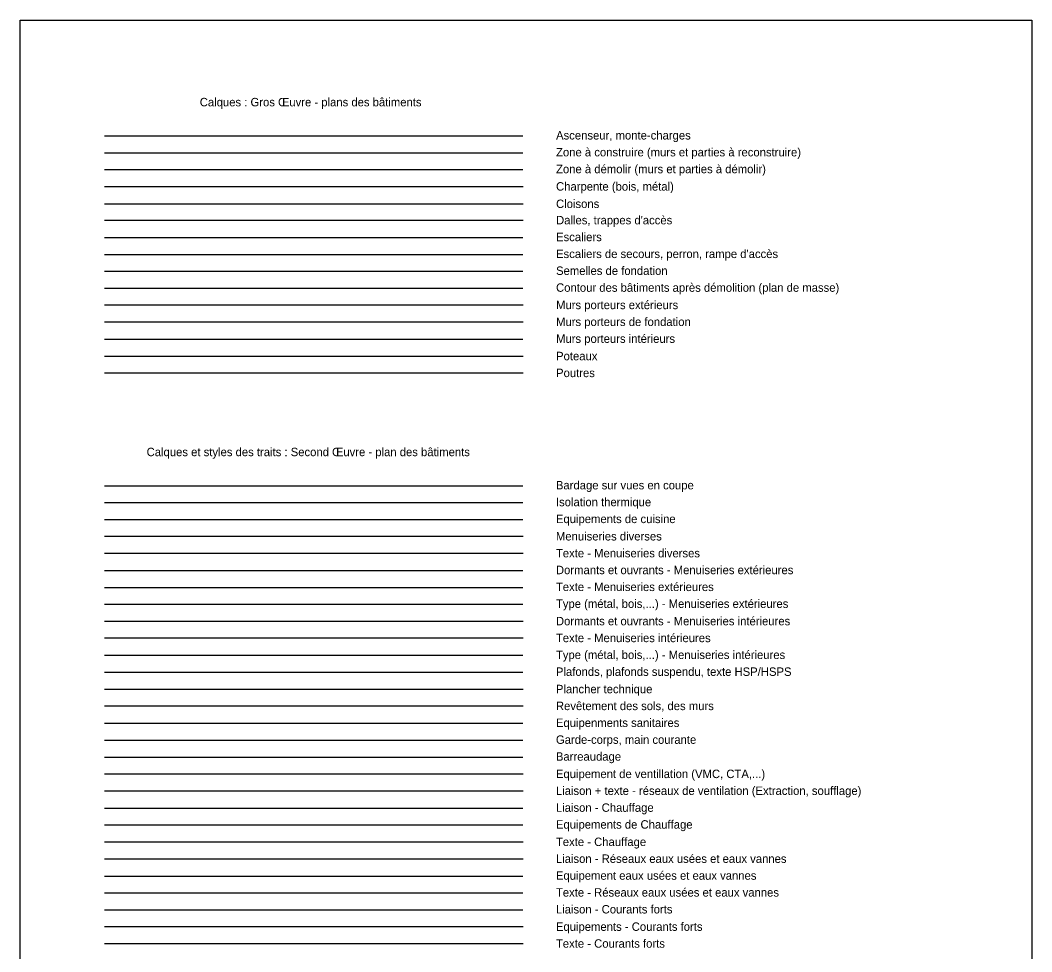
# Model space of a CAD drawing. Extents: x 703432 to 707394, y 7057985 to 7059523.
# Drawn here: x 707334.5 to 707394.5, y 7058589.3 to 7058644.6 of the extents above; entities that cross this region are included whole.
import ezdxf

# ---------------------------------------------------------------- set-up
doc = ezdxf.new("R2010")
doc.units = 0
for name, color, linetype in [('DH_CADRE -CARTOUCHE', 7, 'Continuous'), ('GO_A CONSTRUIRE', 7, 'Continuous'), ('GO_A DEMOLIR', 7, 'Continuous'), ('GO_ASCENSEUR', 7, 'Continuous'), ('GO_BATIMENT_DEMOLI', 7, 'Continuous'), ('GO_CHARPENTE', 7, 'Continuous'), ('GO_CLOISON', 7, 'Continuous'), ('GO_DALLE', 7, 'Continuous'), ('GO_ESCALIER_EXTERIEUR', 7, 'Continuous'), ('GO_ESCALIER_INTERIEUR', 7, 'Continuous'), ('GO_FONDATION', 7, 'Continuous'), ('GO_MUR_EXTERIEUR', 7, 'Continuous'), ('GO_MUR_FONDATION', 7, 'Continuous'), ('GO_MUR_INTERIEUR', 7, 'Continuous'), ('GO_POTEAU', 7, 'Continuous'), ('GO_POUTRE', 7, 'Continuous'), ('SO_BARDAGE', 7, 'Continuous'), ('SO_BARREAUDAGE', 7, 'Continuous'), ('SO_CHAUFFAGE_EQUIP', 7, 'Continuous'), ('SO_CHAUFFAGE_LIAISON', 7, 'Continuous'), ('SO_CHAUFFAGE_TEXTE', 7, 'Continuous'), ('SO_ELEC_C_FORTS_EQUIP', 7, 'Continuous'), ('SO_ELEC_C_FORTS_LIAISON', 7, 'Continuous'), ('SO_ELEC_C_FORTS_TEXTE', 7, 'Continuous'), ('SO_EQUIP_CUISINE', 7, 'Continuous'), ('SO_EU_EV_EQUIP', 7, 'Continuous'), ('SO_EU_EV_LIAISON', 7, 'Continuous'), ('SO_EU_EV_TEXTE', 7, 'Continuous'), ('SO_GARDE_CORPS', 7, 'Continuous'), ('SO_ISOLATION', 7, 'Continuous'), ('SO_MENUISERIE DIVERS_EQUIP', 7, 'Continuous'), ('SO_MENUISERIE DIVERS_TEXTE', 7, 'Continuous'), ('SO_MENUISERIE EXT_ EQUIP', 7, 'Continuous'), ('SO_MENUISERIE EXT_TEXTE', 7, 'Continuous'), ('SO_MENUISERIE EXT_TYPE', 7, 'Continuous'), ('SO_MENUISERIE INT_ EQUIP', 7, 'Continuous'), ('SO_MENUISERIE INT_TEXTE', 7, 'Continuous'), ('SO_MENUISERIE INT_TYPE', 7, 'Continuous'), ('SO_PLAFOND', 7, 'Continuous'), ('SO_PLANCHER TECHNIQUE', 7, 'Continuous'), ('SO_REVETEMENT_SOL_MUR', 7, 'Continuous'), ('SO_SANITAIRE', 7, 'Continuous'), ('SO_VMC_CVC_CTA_EQUIP', 7, 'Continuous'), ('SO_VMC_CVC_CTA_RES-TEXTE', 7, 'Continuous')]:
    doc.layers.add(name, color=color, linetype=linetype)

msp = doc.modelspace()

# ---------------------------------------------------------------- linework, layer by layer
at = {"layer": 'DH_CADRE -CARTOUCHE'}
msp.add_lwpolyline([(707334.469, 7058644.551), (707394.469, 7058644.551), (707394.469, 7058534.551), (707334.469, 7058534.551)], close=True, dxfattribs=at)
at = {"layer": 'GO_A CONSTRUIRE'}
msp.add_line((707339.469, 7058636.694), (707364.284, 7058636.694), dxfattribs=at)
at = {"layer": 'GO_A DEMOLIR'}
msp.add_line((707339.469, 7058635.694), (707364.284, 7058635.694), dxfattribs=at)
at = {"layer": 'GO_ASCENSEUR'}
msp.add_line((707339.469, 7058637.694), (707364.284, 7058637.694), dxfattribs=at)
at = {"layer": 'GO_BATIMENT_DEMOLI'}
msp.add_line((707339.469, 7058628.663), (707364.284, 7058628.663), dxfattribs=at)
at = {"layer": 'GO_CHARPENTE'}
msp.add_line((707339.469, 7058634.694), (707364.298, 7058634.694), dxfattribs=at)
at = {"layer": 'GO_CLOISON'}
msp.add_line((707339.469, 7058633.663), (707364.298, 7058633.663), dxfattribs=at)
at = {"layer": 'GO_DALLE'}
msp.add_line((707339.469, 7058632.694), (707364.298, 7058632.694), dxfattribs=at)
at = {"layer": 'GO_ESCALIER_EXTERIEUR'}
msp.add_line((707339.469, 7058630.663), (707364.284, 7058630.663), dxfattribs=at)
at = {"layer": 'GO_ESCALIER_INTERIEUR'}
msp.add_line((707339.469, 7058631.663), (707364.284, 7058631.663), dxfattribs=at)
at = {"layer": 'GO_FONDATION'}
msp.add_line((707339.469, 7058629.663), (707364.284, 7058629.663), dxfattribs=at)
at = {"layer": 'GO_MUR_EXTERIEUR'}
msp.add_line((707339.469, 7058627.663), (707364.298, 7058627.663), dxfattribs=at)
at = {"layer": 'GO_MUR_FONDATION'}
msp.add_line((707339.469, 7058626.663), (707364.298, 7058626.663), dxfattribs=at)
at = {"layer": 'GO_MUR_INTERIEUR'}
msp.add_line((707339.469, 7058625.632), (707364.284, 7058625.632), dxfattribs=at)
at = {"layer": 'GO_POTEAU'}
msp.add_line((707339.469, 7058624.632), (707364.298, 7058624.632), dxfattribs=at)
at = {"layer": 'GO_POUTRE'}
msp.add_line((707339.469, 7058623.632), (707364.298, 7058623.632), dxfattribs=at)
at = {"layer": 'SO_BARDAGE'}
msp.add_line((707339.462, 7058616.942), (707364.276, 7058616.942), dxfattribs=at)
at = {"layer": 'SO_BARREAUDAGE'}
msp.add_line((707339.462, 7058600.849), (707364.276, 7058600.849), dxfattribs=at)
at = {"layer": 'SO_CHAUFFAGE_EQUIP'}
msp.add_line((707339.462, 7058596.818), (707364.276, 7058596.818), dxfattribs=at)
at = {"layer": 'SO_CHAUFFAGE_LIAISON'}
msp.add_line((707339.462, 7058597.818), (707364.276, 7058597.818), dxfattribs=at)
at = {"layer": 'SO_CHAUFFAGE_TEXTE'}
msp.add_line((707339.462, 7058595.818), (707364.291, 7058595.818), dxfattribs=at)
at = {"layer": 'SO_ELEC_C_FORTS_EQUIP'}
msp.add_line((707339.462, 7058590.787), (707364.291, 7058590.787), dxfattribs=at)
at = {"layer": 'SO_ELEC_C_FORTS_LIAISON'}
msp.add_line((707339.462, 7058591.787), (707364.276, 7058591.787), dxfattribs=at)
at = {"layer": 'SO_ELEC_C_FORTS_TEXTE'}
msp.add_line((707339.462, 7058589.787), (707364.291, 7058589.787), dxfattribs=at)
at = {"layer": 'SO_EQUIP_CUISINE'}
msp.add_line((707339.462, 7058614.942), (707364.276, 7058614.942), dxfattribs=at)
at = {"layer": 'SO_EU_EV_EQUIP'}
msp.add_line((707339.462, 7058593.787), (707364.276, 7058593.787), dxfattribs=at)
at = {"layer": 'SO_EU_EV_LIAISON'}
msp.add_line((707339.462, 7058594.818), (707364.291, 7058594.818), dxfattribs=at)
at = {"layer": 'SO_EU_EV_TEXTE'}
msp.add_line((707339.462, 7058592.787), (707364.276, 7058592.787), dxfattribs=at)
at = {"layer": 'SO_GARDE_CORPS'}
msp.add_line((707339.462, 7058601.849), (707364.276, 7058601.849), dxfattribs=at)
at = {"layer": 'SO_ISOLATION'}
msp.add_line((707339.462, 7058615.942), (707364.276, 7058615.942), dxfattribs=at)
at = {"layer": 'SO_MENUISERIE DIVERS_EQUIP'}
msp.add_line((707339.462, 7058613.942), (707364.291, 7058613.942), dxfattribs=at)
at = {"layer": 'SO_MENUISERIE DIVERS_TEXTE'}
msp.add_line((707339.462, 7058612.942), (707364.291, 7058612.942), dxfattribs=at)
at = {"layer": 'SO_MENUISERIE EXT_ EQUIP'}
msp.add_line((707339.462, 7058611.911), (707364.276, 7058611.911), dxfattribs=at)
at = {"layer": 'SO_MENUISERIE EXT_TEXTE'}
msp.add_line((707339.462, 7058610.911), (707364.276, 7058610.911), dxfattribs=at)
at = {"layer": 'SO_MENUISERIE EXT_TYPE'}
msp.add_line((707339.462, 7058609.911), (707364.276, 7058609.911), dxfattribs=at)
at = {"layer": 'SO_MENUISERIE INT_ EQUIP'}
msp.add_line((707339.462, 7058608.911), (707364.291, 7058608.911), dxfattribs=at)
at = {"layer": 'SO_MENUISERIE INT_TEXTE'}
msp.add_line((707339.462, 7058607.911), (707364.291, 7058607.911), dxfattribs=at)
at = {"layer": 'SO_MENUISERIE INT_TYPE'}
msp.add_line((707339.462, 7058606.88), (707364.276, 7058606.88), dxfattribs=at)
at = {"layer": 'SO_PLAFOND'}
msp.add_line((707339.462, 7058605.88), (707364.276, 7058605.88), dxfattribs=at)
at = {"layer": 'SO_PLANCHER TECHNIQUE'}
msp.add_line((707339.462, 7058604.88), (707364.291, 7058604.88), dxfattribs=at)
at = {"layer": 'SO_REVETEMENT_SOL_MUR'}
msp.add_line((707339.462, 7058603.88), (707364.291, 7058603.88), dxfattribs=at)
at = {"layer": 'SO_SANITAIRE'}
msp.add_line((707339.462, 7058602.849), (707364.276, 7058602.849), dxfattribs=at)
at = {"layer": 'SO_VMC_CVC_CTA_EQUIP'}
msp.add_line((707339.462, 7058599.849), (707364.291, 7058599.849), dxfattribs=at)
at = {"layer": 'SO_VMC_CVC_CTA_RES-TEXTE'}
msp.add_line((707339.462, 7058598.849), (707364.291, 7058598.849), dxfattribs=at)

# ---------------------------------------------------------------- texts
at = {"layer": 'DH_CADRE -CARTOUCHE'}
for s, p in [(' Calques : Gros Œuvre - plans des bâtiments', (707344.932, 7058639.444)), (' Calques et styles des traits : Second Œuvre - plan des bâtiments', (707341.78, 7058618.692))]:
    msp.add_text(s, height=0.5, dxfattribs=at).set_placement(p)
at = {"layer": 'GO_A CONSTRUIRE'}
msp.add_text('Zone à construire (murs et parties à reconstruire)', height=0.5, dxfattribs=at).set_placement((707366.252, 7058636.475))
at = {"layer": 'GO_A DEMOLIR'}
msp.add_text('Zone à démolir (murs et parties à démolir)', height=0.5, dxfattribs=at).set_placement((707366.252, 7058635.475))
at = {"layer": 'GO_ASCENSEUR'}
msp.add_text('Ascenseur, monte-charges', height=0.5, dxfattribs=at).set_placement((707366.252, 7058637.475))
at = {"layer": 'GO_BATIMENT_DEMOLI'}
msp.add_text('Contour des bâtiments après démolition (plan de masse)', height=0.5, dxfattribs=at).set_placement((707366.252, 7058628.444))
at = {"layer": 'GO_CHARPENTE'}
msp.add_text('Charpente (bois, métal)', height=0.5, dxfattribs=at).set_placement((707366.252, 7058634.444))
at = {"layer": 'GO_CLOISON'}
msp.add_text('Cloisons', height=0.5, dxfattribs=at).set_placement((707366.252, 7058633.413))
at = {"layer": 'GO_DALLE'}
msp.add_text("Dalles, trappes d'accès", height=0.5, dxfattribs=at).set_placement((707366.252, 7058632.444))
at = {"layer": 'GO_ESCALIER_EXTERIEUR'}
msp.add_text("Escaliers de secours, perron, rampe d'accès", height=0.5, dxfattribs=at).set_placement((707366.252, 7058630.444))
at = {"layer": 'GO_ESCALIER_INTERIEUR'}
msp.add_text('Escaliers', height=0.5, dxfattribs=at).set_placement((707366.252, 7058631.444))
at = {"layer": 'GO_FONDATION'}
msp.add_text('Semelles de fondation', height=0.5, dxfattribs=at).set_placement((707366.252, 7058629.444))
at = {"layer": 'GO_MUR_EXTERIEUR'}
msp.add_text('Murs porteurs extérieurs', height=0.5, dxfattribs=at).set_placement((707366.252, 7058627.413))
at = {"layer": 'GO_MUR_FONDATION'}
msp.add_text('Murs porteurs de fondation', height=0.5, dxfattribs=at).set_placement((707366.252, 7058626.413))
at = {"layer": 'GO_MUR_INTERIEUR'}
msp.add_text('Murs porteurs intérieurs', height=0.5, dxfattribs=at).set_placement((707366.252, 7058625.413))
at = {"layer": 'GO_POTEAU'}
msp.add_text('Poteaux', height=0.5, dxfattribs=at).set_placement((707366.252, 7058624.382))
at = {"layer": 'GO_POUTRE'}
msp.add_text('Poutres', height=0.5, dxfattribs=at).set_placement((707366.252, 7058623.382))
at = {"layer": 'SO_BARDAGE'}
msp.add_text('Bardage sur vues en coupe', height=0.5, dxfattribs=at).set_placement((707366.244, 7058616.723))
at = {"layer": 'SO_BARREAUDAGE'}
msp.add_text('Barreaudage', height=0.5, dxfattribs=at).set_placement((707366.244, 7058600.63))
at = {"layer": 'SO_CHAUFFAGE_EQUIP'}
msp.add_text('Equipements de Chauffage', height=0.5, dxfattribs=at).set_placement((707366.244, 7058596.599))
at = {"layer": 'SO_CHAUFFAGE_LIAISON'}
msp.add_text('Liaison - Chauffage', height=0.5, dxfattribs=at).set_placement((707366.244, 7058597.599))
at = {"layer": 'SO_CHAUFFAGE_TEXTE'}
msp.add_text('Texte - Chauffage', height=0.5, dxfattribs=at).set_placement((707366.244, 7058595.568))
at = {"layer": 'SO_ELEC_C_FORTS_EQUIP'}
msp.add_text('Equipements - Courants forts', height=0.5, dxfattribs=at).set_placement((707366.244, 7058590.537))
at = {"layer": 'SO_ELEC_C_FORTS_LIAISON'}
msp.add_text('Liaison - Courants forts', height=0.5, dxfattribs=at).set_placement((707366.244, 7058591.568))
at = {"layer": 'SO_ELEC_C_FORTS_TEXTE'}
msp.add_text('Texte - Courants forts', height=0.5, dxfattribs=at).set_placement((707366.244, 7058589.537))
at = {"layer": 'SO_EQUIP_CUISINE'}
msp.add_text('Equipements de cuisine', height=0.5, dxfattribs=at).set_placement((707366.244, 7058614.723))
at = {"layer": 'SO_EU_EV_EQUIP'}
msp.add_text('Equipement eaux usées et eaux vannes', height=0.5, dxfattribs=at).set_placement((707366.244, 7058593.568))
at = {"layer": 'SO_EU_EV_LIAISON'}
msp.add_text('Liaison - Réseaux eaux usées et eaux vannes', height=0.5, dxfattribs=at).set_placement((707366.244, 7058594.568))
at = {"layer": 'SO_EU_EV_TEXTE'}
msp.add_text('Texte - Réseaux eaux usées et eaux vannes', height=0.5, dxfattribs=at).set_placement((707366.244, 7058592.568))
at = {"layer": 'SO_GARDE_CORPS'}
msp.add_text('Garde-corps, main courante', height=0.5, dxfattribs=at).set_placement((707366.244, 7058601.63))
at = {"layer": 'SO_ISOLATION'}
msp.add_text('Isolation thermique', height=0.5, dxfattribs=at).set_placement((707366.244, 7058615.723))
at = {"layer": 'SO_MENUISERIE DIVERS_EQUIP'}
msp.add_text('Menuiseries diverses', height=0.5, dxfattribs=at).set_placement((707366.244, 7058613.692))
at = {"layer": 'SO_MENUISERIE DIVERS_TEXTE'}
msp.add_text('Texte - Menuiseries diverses', height=0.5, dxfattribs=at).set_placement((707366.244, 7058612.692))
at = {"layer": 'SO_MENUISERIE EXT_ EQUIP'}
msp.add_text('Dormants et ouvrants - Menuiseries extérieures', height=0.5, dxfattribs=at).set_placement((707366.244, 7058611.692))
at = {"layer": 'SO_MENUISERIE EXT_TEXTE'}
msp.add_text('Texte - Menuiseries extérieures', height=0.5, dxfattribs=at).set_placement((707366.244, 7058610.692))
at = {"layer": 'SO_MENUISERIE EXT_TYPE'}
msp.add_text('Type (métal, bois,...) - Menuiseries extérieures', height=0.5, dxfattribs=at).set_placement((707366.244, 7058609.692))
at = {"layer": 'SO_MENUISERIE INT_ EQUIP'}
msp.add_text('Dormants et ouvrants - Menuiseries intérieures', height=0.5, dxfattribs=at).set_placement((707366.244, 7058608.661))
at = {"layer": 'SO_MENUISERIE INT_TEXTE'}
msp.add_text('Texte - Menuiseries intérieures', height=0.5, dxfattribs=at).set_placement((707366.244, 7058607.661))
at = {"layer": 'SO_MENUISERIE INT_TYPE'}
msp.add_text('Type (métal, bois,...) - Menuiseries intérieures', height=0.5, dxfattribs=at).set_placement((707366.244, 7058606.661))
at = {"layer": 'SO_PLAFOND'}
msp.add_text('Plafonds, plafonds suspendu, texte HSP/HSPS', height=0.5, dxfattribs=at).set_placement((707366.244, 7058605.661))
at = {"layer": 'SO_PLANCHER TECHNIQUE'}
msp.add_text('Plancher technique', height=0.5, dxfattribs=at).set_placement((707366.244, 7058604.63))
at = {"layer": 'SO_REVETEMENT_SOL_MUR'}
msp.add_text('Revêtement des sols, des murs', height=0.5, dxfattribs=at).set_placement((707366.244, 7058603.63))
at = {"layer": 'SO_SANITAIRE'}
msp.add_text('Equipenments sanitaires', height=0.5, dxfattribs=at).set_placement((707366.244, 7058602.63))
at = {"layer": 'SO_VMC_CVC_CTA_EQUIP'}
msp.add_text('Equipement de ventillation (VMC, CTA,...)', height=0.5, dxfattribs=at).set_placement((707366.244, 7058599.599))
at = {"layer": 'SO_VMC_CVC_CTA_RES-TEXTE'}
msp.add_text('Liaison + texte - réseaux de ventilation (Extraction, soufflage)', height=0.5, dxfattribs=at).set_placement((707366.244, 7058598.599))

doc.saveas('drawing.dxf')
